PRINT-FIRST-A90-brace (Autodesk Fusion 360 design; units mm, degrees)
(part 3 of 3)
extrude "Extrude2" cut sketch "E Rear Bearing Cap Bolt seed" profile of C1 along normal blind 3 (= "capThickness")
circular_pattern "C-Pattern1" TotalAngle 360
chamfer "Chamfer1" distance 0.3 (= "bedRelief")
work_plane "WorkPlane1" AlongDistance -29 (= "hubFace - adapterThickness") ExtraOffset 0
sketch "F Adapter Flange sketch" plane through (-20.5061, -20.5061, 0) normal (0.7071, 0.7071, 0) x axis (0, 0, 1)
  circle C1 centre (0, 0) radius 38
  dimension "d967" diameter C1 = 76 (= "mountOD")
extrude "Extrude1" new body sketch "F Adapter Flange sketch" along normal blind 6 (= "adapterThickness")
work_plane "WorkPlane2" AlongDistance -23 (= "hubFace") ExtraOffset 0
sketch "F Centering Pilot sketch" plane through (-16.2635, -16.2635, 0) normal (0.7071, 0.7071, 0) x axis (0, 0, 1)
  circle C1 centre (0, 0) radius 25
  circle C2 centre (0, 0) radius 17
  dimension "d972" diameter C1 = 50 (= "pilotDiameter")
  dimension "d973" diameter C2 = 34 (= "pilotInside")
extrude "Extrude2" add sketch "F Centering Pilot sketch" along normal blind 2 (= "pilotHeight")
work_plane "WorkPlane3" AlongDistance -29 (= "hubFace - adapterThickness") ExtraOffset 0
sketch "F Shaft Clearance sketch" plane through (-20.5061, -20.5061, 0) normal (0.7071, 0.7071, 0) x axis (0, 0, 1)
  circle C1 centre (0, 0) radius 4.25
  dimension "d978" diameter C1 = 8.5 (= "shaftClearance")
extrude "Extrude3" cut sketch "F Shaft Clearance sketch" along normal blind 6 (= "adapterThickness")
work_plane "WorkPlane4" AlongDistance -29 (= "hubFace - adapterThickness") ExtraOffset 0
sketch "F Mount Holes" plane through (-20.5061, -20.5061, 0) normal (0.7071, 0.7071, 0) x axis (0, 0, 1)
  circle C1 centre (22.6274, 22.6274) radius 2.15
  circle C2 centre (-22.6274, 22.6274) radius 2.15
  circle C3 centre (-22.6274, -22.6274) radius 2.15
  circle C4 centre (22.6274, -22.6274) radius 2.15
  point P1 (0, 0)
  point P2 (22.6274, 22.6274)
  point P3 (-22.6274, 22.6274)
  point P4 (-22.6274, -22.6274)
  point P5 (22.6274, -22.6274)
  dimension "d983" distance P1 P2 = 22.6274 (= "abs(mountCircle / ( 2 * sqrt(2) ))")
  dimension "d984" distance P1 P2 = 22.6274 (= "abs(mountCircle / ( 2 * sqrt(2) ))")
  dimension "d985" diameter C1 = 4.3 (= "m4Clearance")
  dimension "d986" distance P1 P3 = 22.6274 (= "abs(-mountCircle / ( 2 * sqrt(2) ))")
  dimension "d987" distance P1 P3 = 22.6274 (= "abs(mountCircle / ( 2 * sqrt(2) ))")
  dimension "d988" diameter C2 = 4.3 (= "m4Clearance")
  dimension "d989" distance P1 P4 = 22.6274 (= "abs(-mountCircle / ( 2 * sqrt(2) ))")
  dimension "d990" distance P1 P4 = 22.6274 (= "abs(-mountCircle / ( 2 * sqrt(2) ))")
  dimension "d991" diameter C3 = 4.3 (= "m4Clearance")
  dimension "d992" distance P1 P5 = 22.6274 (= "abs(mountCircle / ( 2 * sqrt(2) ))")
  dimension "d993" distance P1 P5 = 22.6274 (= "abs(-mountCircle / ( 2 * sqrt(2) ))")
  dimension "d994" diameter C4 = 4.3 (= "m4Clearance")
extrude "Extrude4" cut sketch "F Mount Holes" along normal blind 6 (= "adapterThickness")
sketch "F Compression Sleeve Holes" plane through (-20.5061, -20.5061, 0) normal (0.7071, 0.7071, 0) x axis (0, 0, 1)
  line L1 (11.3137, 0) -> (0, 0)
  line L2 (0, 11.3137) -> (0, 0)
  line L3 (-11.3137, 0) -> (0, 0)
  line L4 (0, -11.3137) -> (0, 0)
  circle C1 centre (11.3137, 0) radius 4.1
  circle C2 centre (0, 11.3137) radius 4.1
  circle C3 centre (-11.3137, 0) radius 4.1
  circle C4 centre (0, -11.3137) radius 4.1
  point P1 (0, 0)
  point P2 (11.3137, 0)
  point P3 (0, 11.3137)
  point P5 (0, -11.3137)
  horizontal L1
  vertical L2
  horizontal L3
  vertical L4
  dimension "d997" distance P1 P2 = 11.3137 (= "abs(hubHoleSpacing / sqrt(2))")
  dimension "d998" diameter C1 = 8.2 (= "sleeveOD + sleeveAllowance")
  dimension "d999" distance P1 P3 = 11.3137 (= "abs(hubHoleSpacing / sqrt(2))")
  dimension "d1000" diameter C2 = 8.2 (= "sleeveOD + sleeveAllowance")
  dimension "d59" = 150 (= "bodyWidth")
  dimension "d1002" diameter C3 = 8.2 (= "sleeveOD + sleeveAllowance")
  dimension "d1003" distance P1 P5 = 11.3137 (= "abs(-hubHoleSpacing / sqrt(2))")
  dimension "d1004" diameter C4 = 8.2 (= "sleeveOD + sleeveAllowance")
  dimension "d1001" distance = 11.3137 (= "abs(-hubHoleSpacing / sqrt(2))")
extrude "Extrude5" cut sketch "F Compression Sleeve Holes" profile of C1 C2 C3 C4 along normal blind 6 (= "adapterThickness")
chamfer "Chamfer1" distance 0.4 (= "entryChamfer")
chamfer "Chamfer2" distance 0.3 (= "bedRelief")
work_plane "WorkPlane1" AlongDistance 0.5 (= "qFront") ExtraOffset 0
sketch "Front 608 sketch" plane through (0.3536, 0.3536, 0) normal (0.7071, 0.7071, 0) x axis (0, 0, 1)
  circle C1 centre (0, 0) radius 11
  circle C2 centre (0, 0) radius 4
  dimension "d1011" diameter C1 = 22 (= "bearingOD")
  dimension "d1012" diameter C2 = 8 (= "bearingID")
extrude "Extrude1" new body sketch "Front 608 sketch" along normal blind 7 (= "bearingWidth")
work_plane "WorkPlane2" AlongDistance 25.6 (= "qRearBearing") ExtraOffset 0
sketch "Rear 608 sketch" plane through (18.1019, 18.1019, 0) normal (0.7071, 0.7071, 0) x axis (0, 0, 1)
  circle C1 centre (0, 0) radius 11
  circle C2 centre (0, 0) radius 4
  dimension "d1017" diameter C1 = 22 (= "bearingOD")
  dimension "d1018" diameter C2 = 8 (= "bearingID")
extrude "Extrude2" new body sketch "Rear 608 sketch" along normal blind 7 (= "bearingWidth")
work_plane "WorkPlane1" AlongDistance -24 ExtraOffset 0
sketch "Metal Shaft sketch" plane through (-16.9706, -16.9706, 0) normal (0.7071, 0.7071, 0) x axis (0, 0, 1)
  circle C1 centre (0, 0) radius 4
  dimension "d1023" diameter C1 = 8
extrude "Extrude1" new body sketch "Metal Shaft sketch" along normal blind 60
work_plane "WorkPlane1" AlongDistance -3.5 (= "qFront - 4 mm") ExtraOffset 0
sketch "Front Inner Ring Spacer sketch" plane through (-2.4749, -2.4749, 0) normal (0.7071, 0.7071, 0) x axis (0, 0, 1)
  circle C1 centre (0, 0) radius 5
  circle C2 centre (0, 0) radius 4
  dimension "d1028" diameter C1 = 10
  dimension "d1029" diameter C2 = 8
extrude "Extrude1" new body sketch "Front Inner Ring Spacer sketch" along normal blind 4
work_plane "WorkPlane2" AlongDistance 7.5 (= "qFront + bearingWidth") ExtraOffset 0
sketch "Rear Inner Ring Spacer sketch" plane through (5.3033, 5.3033, 0) normal (0.7071, 0.7071, 0) x axis (0, 0, 1)
  circle C1 centre (0, 0) radius 5
  circle C2 centre (0, 0) radius 4
  dimension "d1034" diameter C1 = 10
  dimension "d1035" diameter C2 = 8
extrude "Extrude2" new body sketch "Rear Inner Ring Spacer sketch" along normal blind 4
work_plane "WorkPlane1" AlongDistance -12.5 (= "qFront - 13 mm") ExtraOffset 0
sketch "Front Collar Maximum Envelope sketch" plane through (-8.8388, -8.8388, 0) normal (0.7071, 0.7071, 0) x axis (0, 0, 1)
  circle C1 centre (0, 0) radius 11.2
  circle C2 centre (0, 0) radius 4
  dimension "d1040" diameter C1 = 22.4
  dimension "d1041" diameter C2 = 8
extrude "Extrude1" new body sketch "Front Collar Maximum Envelope sketch" along normal blind 9
work_plane "WorkPlane2" AlongDistance 11.5 (= "qFront + bearingWidth + 4 mm") ExtraOffset 0
sketch "Rear Collar Maximum Envelope sketch" plane through (8.1317, 8.1317, 0) normal (0.7071, 0.7071, 0) x axis (0, 0, 1)
  circle C1 centre (0, 0) radius 11.2
  circle C2 centre (0, 0) radius 4
  dimension "d1046" diameter C1 = 22.4
  dimension "d1047" diameter C2 = 8
extrude "Extrude2" new body sketch "Rear Collar Maximum Envelope sketch" along normal blind 9
work_plane "WorkPlane1" AlongDistance 0 ExtraOffset 0
sketch "Spacer Pattern Axis" plane through (0, 0, 0) normal (0.7071, 0.7071, 0) x axis (0, 0, 1)
  circle C1 centre (0, 0) radius 0.5
  dimension "d1052" diameter C1 = 1
work_plane "WorkPlane2" AlongDistance 10.6 (= "qFrontBack") ExtraOffset 0
sketch "Support Spacer OD" plane through (7.4953, 7.4953, 0) normal (0.7071, 0.7071, 0) x axis (0, 0, 1)
  line L1 (17, 0) -> (0, 0)
  circle C1 centre (17, 0) radius 3
  circle C2 centre (17, 0) radius 1.6
  point P1 (0, 0)
  point P2 (17, 0)
  horizontal L1
  dimension "d1055" distance P1 P2 = 17 (= "supportCircle / 2")
  dimension "d1056" diameter C1 = 6 (= "supportSpacerOD")
  dimension "d1057" diameter C2 = 3.2
extrude "Extrude1" new body sketch "Support Spacer OD" profile of C1 C2 along normal blind 12 (= "supportSpacer")
circular_pattern "C-Pattern1" TotalAngle 360
work_plane "WorkPlane1" AlongDistance -29 (= "hubFace - adapterThickness") ExtraOffset 0
sketch "Sleeve 1 Outer" plane through (-20.5061, -20.5061, 0) normal (0.7071, 0.7071, 0) x axis (0, 0, 1)
  line L1 (11.3137, 0) -> (0, 0)
  circle C1 centre (11.3137, 0) radius 4
  circle C2 centre (11.3137, 0) radius 2.15
  point P1 (0, 0)
  point P2 (11.3137, 0)
  horizontal L1
  dimension "d1064" distance P1 P2 = 11.3137 (= "abs(hubHoleSpacing / sqrt(2))")
  dimension "d1065" diameter C1 = 8 (= "sleeveOD")
  dimension "d1066" diameter C2 = 4.3
extrude "Extrude1" new body sketch "Sleeve 1 Outer" profile of C1 C2 along normal blind 6 (= "adapterThickness")
work_plane "WorkPlane2" AlongDistance -29 (= "hubFace - adapterThickness") ExtraOffset 0
sketch "Sleeve 2 Outer" plane through (-20.5061, -20.5061, 0) normal (0.7071, 0.7071, 0) x axis (0, 0, 1)
  line L1 (0, 11.3137) -> (0, 0)
  circle C1 centre (0, 11.3137) radius 4
  circle C2 centre (0, 11.3137) radius 2.15
  point P1 (0, 0)
  point P2 (0, 11.3137)
  vertical L1
  dimension "d1071" distance P1 P2 = 11.3137 (= "abs(hubHoleSpacing / sqrt(2))")
  dimension "d1072" diameter C1 = 8 (= "sleeveOD")
  dimension "d1073" diameter C2 = 4.3
extrude "Extrude2" new body sketch "Sleeve 2 Outer" profile of C1 C2 along normal blind 6 (= "adapterThickness")
work_plane "WorkPlane3" AlongDistance -29 (= "hubFace - adapterThickness") ExtraOffset 0
sketch "Sleeve 3 Outer" plane through (-20.5061, -20.5061, 0) normal (0.7071, 0.7071, 0) x axis (0, 0, 1)
  line L1 (-11.3137, 0) -> (0, 0)
  circle C1 centre (-11.3137, 0) radius 4
  circle C2 centre (-11.3137, 0) radius 2.15
  point P1 (0, 0)
  point P2 (-11.3137, 0)
  horizontal L1
  dimension "d1078" distance P1 P2 = 11.3137 (= "abs(-hubHoleSpacing / sqrt(2))")
  dimension "d1079" diameter C1 = 8 (= "sleeveOD")
  dimension "d1080" diameter C2 = 4.3
extrude "Extrude3" new body sketch "Sleeve 3 Outer" profile of C1 C2 along normal blind 6 (= "adapterThickness")
work_plane "WorkPlane4" AlongDistance -29 (= "hubFace - adapterThickness") ExtraOffset 0
sketch "Sleeve 4 Outer" plane through (-20.5061, -20.5061, 0) normal (0.7071, 0.7071, 0) x axis (0, 0, 1)
  line L1 (0, -11.3137) -> (0, 0)
  circle C1 centre (0, -11.3137) radius 4
  circle C2 centre (0, -11.3137) radius 2.15
  point P1 (0, 0)
  point P2 (0, -11.3137)
  vertical L1
  dimension "d1085" distance P1 P2 = 11.3137 (= "abs(-hubHoleSpacing / sqrt(2))")
  dimension "d1086" diameter C1 = 8 (= "sleeveOD")
  dimension "d1087" diameter C2 = 4.3
extrude "Extrude4" new body sketch "Sleeve 4 Outer" profile of C1 C2 along normal blind 6 (= "adapterThickness")
work_plane "WorkPlane1" AlongDistance -23 (= "hubFace") ExtraOffset 0
sketch "Sonic Hub Body sketch" plane through (-16.2635, -16.2635, 0) normal (0.7071, 0.7071, 0) x axis (0, 0, 1)
  circle C1 centre (0, 0) radius 16
  circle C2 centre (0, 0) radius 4
  dimension "d1092" diameter C1 = 32
  dimension "d1093" diameter C2 = 8
extrude "Extrude1" new body sketch "Sonic Hub Body sketch" along normal blind 8
work_plane "WorkPlane2" AlongDistance -15 (= "hubFace + 8 mm") ExtraOffset 0
sketch "Sonic Hub Pilot sketch" plane through (-10.6066, -10.6066, 0) normal (0.7071, 0.7071, 0) x axis (0, 0, 1)
  circle C1 centre (0, 0) radius 7
  circle C2 centre (0, 0) radius 4
  dimension "d1098" diameter C1 = 14
  dimension "d1099" diameter C2 = 8
extrude "Extrude2" add sketch "Sonic Hub Pilot sketch" along normal blind 2
work_plane "WorkPlane3" AlongDistance -23 (= "hubFace") ExtraOffset 0
sketch "Hub M4 Thread Envelopes" plane through (-16.2635, -16.2635, 0) normal (0.7071, 0.7071, 0) x axis (0, 0, 1)
  line L1 (11.3137, 0) -> (0, 0)
  line L2 (0, 11.3137) -> (0, 0)
  line L3 (-11.3137, 0) -> (0, 0)
  line L4 (0, -11.3137) -> (0, 0)
  circle C1 centre (11.3137, 0) radius 2.15
  circle C2 centre (0, 11.3137) radius 2.15
  circle C3 centre (-11.3137, 0) radius 2.15
  circle C4 centre (0, -11.3137) radius 2.15
  point P1 (0, 0)
  point P2 (11.3137, 0)
  point P3 (0, 11.3137)
  point P5 (0, -11.3137)
  horizontal L1
  vertical L2
  horizontal L3
  vertical L4
  dimension "d1104" distance P1 P2 = 11.3137 (= "abs(hubHoleSpacing / sqrt(2))")
  dimension "d1105" diameter C1 = 4.3
  dimension "d1106" distance P1 P3 = 11.3137 (= "abs(hubHoleSpacing / sqrt(2))")
  dimension "d1107" diameter C2 = 4.3
  dimension "d59" = 150 (= "bodyWidth")
  dimension "d1109" diameter C3 = 4.3
  dimension "d1110" distance P1 P5 = 11.3137 (= "abs(-hubHoleSpacing / sqrt(2))")
  dimension "d1111" diameter C4 = 4.3
  dimension "d1108" distance = 11.3137 (= "abs(-hubHoleSpacing / sqrt(2))")
extrude "Extrude3" cut sketch "Hub M4 Thread Envelopes" profile of C1 C2 C3 C4 along normal blind 8
work_plane "WorkPlane1" AlongDistance -30 (= "hubFace - adapterThickness - 1 mm") ExtraOffset 0
sketch "Hub Screw 1 Profile" plane through (-21.2132, -21.2132, 0) normal (0.7071, 0.7071, 0) x axis (0, 0, 1)
  line L1 (11.3137, 0) -> (0, 0)
  circle C1 centre (11.3137, 0) radius 2
  point P1 (0, 0)
  point P2 (11.3137, 0)
  horizontal L1
  dimension "d1116" distance P1 P2 = 11.3137 (= "abs(hubHoleSpacing / sqrt(2))")
  dimension "d1117" diameter C1 = 4
extrude "Extrude1" new body sketch "Hub Screw 1 Profile" profile of C1 along normal blind 12
work_plane "WorkPlane2" AlongDistance -34 (= "hubFace - adapterThickness - 5 mm") ExtraOffset 0
sketch "Hub Screw Head 1 Profile" plane through (-24.0416, -24.0416, 0) normal (0.7071, 0.7071, 0) x axis (0, 0, 1)
  line L1 (11.3137, 0) -> (0, 0)
  circle C1 centre (11.3137, 0) radius 3.5
  point P1 (0, 0)
  point P2 (11.3137, 0)
  horizontal L1
  dimension "d1122" distance P1 P2 = 11.3137 (= "abs(hubHoleSpacing / sqrt(2))")
  dimension "d1123" diameter C1 = 7
extrude "Extrude2" new body sketch "Hub Screw Head 1 Profile" profile of C1 along normal blind 4
work_plane "WorkPlane3" AlongDistance -30 (= "hubFace - adapterThickness - 1 mm") ExtraOffset 0
sketch "Hub Washer 1 Outer" plane through (-21.2132, -21.2132, 0) normal (0.7071, 0.7071, 0) x axis (0, 0, 1)
  line L1 (11.3137, 0) -> (0, 0)
  circle C1 centre (11.3137, 0) radius 6
  circle C2 centre (11.3137, 0) radius 2.15
  point P1 (0, 0)
  point P2 (11.3137, 0)
  horizontal L1
  dimension "d1128" distance P1 P2 = 11.3137 (= "abs(hubHoleSpacing / sqrt(2))")
  dimension "d1129" diameter C1 = 12
  dimension "d1130" diameter C2 = 4.3
extrude "Extrude3" new body sketch "Hub Washer 1 Outer" profile of C1 C2 along normal blind 1
work_plane "WorkPlane4" AlongDistance -30 (= "hubFace - adapterThickness - 1 mm") ExtraOffset 0
sketch "Hub Screw 2 Profile" plane through (-21.2132, -21.2132, 0) normal (0.7071, 0.7071, 0) x axis (0, 0, 1)
  line L1 (0, 11.3137) -> (0, 0)
  circle C1 centre (0, 11.3137) radius 2
  point P1 (0, 0)
  point P2 (0, 11.3137)
  vertical L1
  dimension "d1135" distance P1 P2 = 11.3137 (= "abs(hubHoleSpacing / sqrt(2))")
  dimension "d1136" diameter C1 = 4
extrude "Extrude4" new body sketch "Hub Screw 2 Profile" profile of C1 along normal blind 12
work_plane "WorkPlane5" AlongDistance -34 (= "hubFace - adapterThickness - 5 mm") ExtraOffset 0
sketch "Hub Screw Head 2 Profile" plane through (-24.0416, -24.0416, 0) normal (0.7071, 0.7071, 0) x axis (0, 0, 1)
  line L1 (0, 11.3137) -> (0, 0)
  circle C1 centre (0, 11.3137) radius 3.5
  point P1 (0, 0)
  point P2 (0, 11.3137)
  vertical L1
  dimension "d1141" distance P1 P2 = 11.3137 (= "abs(hubHoleSpacing / sqrt(2))")
  dimension "d1142" diameter C1 = 7
extrude "Extrude5" new body sketch "Hub Screw Head 2 Profile" profile of C1 along normal blind 4
work_plane "WorkPlane6" AlongDistance -30 (= "hubFace - adapterThickness - 1 mm") ExtraOffset 0
sketch "Hub Washer 2 Outer" plane through (-21.2132, -21.2132, 0) normal (0.7071, 0.7071, 0) x axis (0, 0, 1)
  line L1 (0, 11.3137) -> (0, 0)
  circle C1 centre (0, 11.3137) radius 6
  circle C2 centre (0, 11.3137) radius 2.15
  point P1 (0, 0)
  point P2 (0, 11.3137)
  vertical L1
  dimension "d1147" distance P1 P2 = 11.3137 (= "abs(hubHoleSpacing / sqrt(2))")
  dimension "d1148" diameter C1 = 12
  dimension "d1149" diameter C2 = 4.3
extrude "Extrude6" new body sketch "Hub Washer 2 Outer" profile of C1 C2 along normal blind 1
work_plane "WorkPlane7" AlongDistance -30 (= "hubFace - adapterThickness - 1 mm") ExtraOffset 0
sketch "Hub Screw 3 Profile" plane through (-21.2132, -21.2132, 0) normal (0.7071, 0.7071, 0) x axis (0, 0, 1)
  line L1 (-11.3137, 0) -> (0, 0)
  circle C1 centre (-11.3137, 0) radius 2
  point P1 (0, 0)
  point P2 (-11.3137, 0)
  horizontal L1
  dimension "d1154" distance P1 P2 = 11.3137 (= "abs(-hubHoleSpacing / sqrt(2))")
  dimension "d1155" diameter C1 = 4
extrude "Extrude7" new body sketch "Hub Screw 3 Profile" profile of C1 along normal blind 12
work_plane "WorkPlane8" AlongDistance -34 (= "hubFace - adapterThickness - 5 mm") ExtraOffset 0
sketch "Hub Screw Head 3 Profile" plane through (-24.0416, -24.0416, 0) normal (0.7071, 0.7071, 0) x axis (0, 0, 1)
  line L1 (-11.3137, 0) -> (0, 0)
  circle C1 centre (-11.3137, 0) radius 3.5
  point P1 (0, 0)
  point P2 (-11.3137, 0)
  horizontal L1
  dimension "d1160" distance P1 P2 = 11.3137 (= "abs(-hubHoleSpacing / sqrt(2))")
  dimension "d1161" diameter C1 = 7
extrude "Extrude8" new body sketch "Hub Screw Head 3 Profile" profile of C1 along normal blind 4
work_plane "WorkPlane9" AlongDistance -30 (= "hubFace - adapterThickness - 1 mm") ExtraOffset 0
sketch "Hub Washer 3 Outer" plane through (-21.2132, -21.2132, 0) normal (0.7071, 0.7071, 0) x axis (0, 0, 1)
  line L1 (-11.3137, 0) -> (0, 0)
  circle C1 centre (-11.3137, 0) radius 6
  circle C2 centre (-11.3137, 0) radius 2.15
  point P1 (0, 0)
  point P2 (-11.3137, 0)
  horizontal L1
  dimension "d1166" distance P1 P2 = 11.3137 (= "abs(-hubHoleSpacing / sqrt(2))")
  dimension "d1167" diameter C1 = 12
  dimension "d1168" diameter C2 = 4.3
extrude "Extrude9" new body sketch "Hub Washer 3 Outer" profile of C1 C2 along normal blind 1
work_plane "WorkPlane10" AlongDistance -30 (= "hubFace - adapterThickness - 1 mm") ExtraOffset 0
sketch "Hub Screw 4 Profile" plane through (-21.2132, -21.2132, 0) normal (0.7071, 0.7071, 0) x axis (0, 0, 1)
  line L1 (0, -11.3137) -> (0, 0)
  circle C1 centre (0, -11.3137) radius 2
  point P1 (0, 0)
  point P2 (0, -11.3137)
  vertical L1
  dimension "d1173" distance P1 P2 = 11.3137 (= "abs(-hubHoleSpacing / sqrt(2))")
  dimension "d1174" diameter C1 = 4
extrude "Extrude10" new body sketch "Hub Screw 4 Profile" profile of C1 along normal blind 12
work_plane "WorkPlane11" AlongDistance -34 (= "hubFace - adapterThickness - 5 mm") ExtraOffset 0
sketch "Hub Screw Head 4 Profile" plane through (-24.0416, -24.0416, 0) normal (0.7071, 0.7071, 0) x axis (0, 0, 1)
  line L1 (0, -11.3137) -> (0, 0)
  circle C1 centre (0, -11.3137) radius 3.5
  point P1 (0, 0)
  point P2 (0, -11.3137)
  vertical L1
  dimension "d1179" distance P1 P2 = 11.3137 (= "abs(-hubHoleSpacing / sqrt(2))")
  dimension "d1180" diameter C1 = 7
extrude "Extrude11" new body sketch "Hub Screw Head 4 Profile" profile of C1 along normal blind 4
work_plane "WorkPlane12" AlongDistance -30 (= "hubFace - adapterThickness - 1 mm") ExtraOffset 0
sketch "Hub Washer 4 Outer" plane through (-21.2132, -21.2132, 0) normal (0.7071, 0.7071, 0) x axis (0, 0, 1)
  line L1 (0, -11.3137) -> (0, 0)
  circle C1 centre (0, -11.3137) radius 6
  circle C2 centre (0, -11.3137) radius 2.15
  point P1 (0, 0)
  point P2 (0, -11.3137)
  vertical L1
  dimension "d1185" distance P1 P2 = 11.3137 (= "abs(-hubHoleSpacing / sqrt(2))")
  dimension "d1186" diameter C1 = 12
  dimension "d1187" diameter C2 = 4.3
extrude "Extrude12" new body sketch "Hub Washer 4 Outer" profile of C1 C2 along normal blind 1
work_plane "WorkPlane1" AlongDistance -30 (= "hubFace - adapterThickness - 1 mm") ExtraOffset 0
sketch "Adapter Screw 1 Profile" plane through (-21.2132, -21.2132, 0) normal (0.7071, 0.7071, 0) x axis (0, 0, 1)
  circle C1 centre (22.6274, 22.6274) radius 2
  point P1 (0, 0)
  point P2 (22.6274, 22.6274)
  dimension "d1192" distance P1 P2 = 22.6274 (= "abs(mountCircle / ( 2 * sqrt(2) ))")
  dimension "d1193" distance P1 P2 = 22.6274 (= "abs(mountCircle / ( 2 * sqrt(2) ))")
  dimension "d1194" diameter C1 = 4
extrude "Extrude1" new body sketch "Adapter Screw 1 Profile" along normal blind 30
work_plane "WorkPlane2" AlongDistance -34 (= "hubFace - adapterThickness - 5 mm") ExtraOffset 0
sketch "Adapter Screw Head 1 Profile" plane through (-24.0416, -24.0416, 0) normal (0.7071, 0.7071, 0) x axis (0, 0, 1)
  circle C1 centre (22.6274, 22.6274) radius 3.5
  point P1 (0, 0)
  point P2 (22.6274, 22.6274)
  dimension "d1199" distance P1 P2 = 22.6274 (= "abs(mountCircle / ( 2 * sqrt(2) ))")
  dimension "d1200" distance P1 P2 = 22.6274 (= "abs(mountCircle / ( 2 * sqrt(2) ))")
  dimension "d1201" diameter C1 = 7
extrude "Extrude2" new body sketch "Adapter Screw Head 1 Profile" along normal blind 4
work_plane "WorkPlane3" AlongDistance -30 (= "hubFace - adapterThickness - 1 mm") ExtraOffset 0
sketch "Adapter Washer 1 Outer" plane through (-21.2132, -21.2132, 0) normal (0.7071, 0.7071, 0) x axis (0, 0, 1)
  circle C1 centre (22.6274, 22.6274) radius 4.5
  circle C2 centre (22.6274, 22.6274) radius 2.15
  point P1 (0, 0)
  point P2 (22.6274, 22.6274)
  dimension "d1206" distance P1 P2 = 22.6274 (= "abs(mountCircle / ( 2 * sqrt(2) ))")
  dimension "d1207" distance P1 P2 = 22.6274 (= "abs(mountCircle / ( 2 * sqrt(2) ))")
  dimension "d1208" diameter C1 = 9
  dimension "d1209" diameter C2 = 4.3
extrude "Extrude3" new body sketch "Adapter Washer 1 Outer" along normal blind 1
work_plane "WorkPlane4" ExtraOffset 0
sketch "Adapter Nut Hex 1" plane through (-3.182, -3.182, 0) normal (0.7071, 0.7071, 0) x axis (0, 0, 1)
  line L1 (24.6481, 26.1274) -> (26.6689, 22.6274)
  line L2 (20.6067, 26.1274) -> (24.6481, 26.1274)
  line L3 (18.586, 22.6274) -> (20.6067, 26.1274)
  line L4 (20.6067, 19.1274) -> (18.586, 22.6274)
  line L5 (24.6481, 19.1274) -> (20.6067, 19.1274)
  line L6 (26.6689, 22.6274) -> (24.6481, 19.1274)
  circle C1 centre (22.6274, 22.6274) radius 4.0415
  point P3 (26.6689, 22.6274)
  point P4 (24.6481, 26.1274)
  point P5 (20.6067, 26.1274)
  point P6 (18.586, 22.6274)
  point P7 (20.6067, 19.1274)
  point P8 (24.6481, 19.1274)
  point P1 (0, 0)
  point P2 (22.6274, 22.6274)
  coincident C1 P3
  coincident C1 P4
  coincident C1 P5
  coincident C1 P6
  coincident C1 P7
  coincident C1 P8
  equal L1 L2
  equal L1 L3
  equal L1 L4
  equal L1 L5
  equal L1 L6
  horizontal L2
  dimension "d1214" distance P1 P2 = 22.6274 (= "abs(mountCircle / ( 2 * sqrt(2) ))")
  dimension "d1215" distance P1 P2 = 22.6274 (= "abs(mountCircle / ( 2 * sqrt(2) ))")
  dimension "d1216" diameter C1 = 8.0829 (= "2 * ( 7 mm ) / sqrt(3)")
extrude "Extrude4" new body sketch "Adapter Nut Hex 1" profile of L1 L2 L3 L4 L5 L6 along normal blind 3.2
sketch "Nut Thread Clearance 1" plane through (-3.182, -3.182, 0) normal (0.7071, 0.7071, 0) x axis (0, 0, 1)
  circle C1 centre (22.6274, 22.6274) radius 2.15
  point P1 (0, 0)
  point P2 (22.6274, 22.6274)
  dimension "d1219" distance P1 P2 = 22.6274 (= "abs(mountCircle / ( 2 * sqrt(2) ))")
  dimension "d1220" distance P1 P2 = 22.6274 (= "abs(mountCircle / ( 2 * sqrt(2) ))")
  dimension "d1221" diameter C1 = 4.3
extrude "Extrude5" cut sketch "Nut Thread Clearance 1" along normal blind 3.2
work_plane "WorkPlane5" AlongDistance -30 (= "hubFace - adapterThickness - 1 mm") ExtraOffset 0
sketch "Adapter Screw 2 Profile" plane through (-21.2132, -21.2132, 0) normal (0.7071, 0.7071, 0) x axis (0, 0, 1)
  circle C1 centre (-22.6274, 22.6274) radius 2
  point P1 (0, 0)
  point P2 (-22.6274, 22.6274)
  dimension "d1226" distance P1 P2 = 22.6274 (= "abs(-mountCircle / ( 2 * sqrt(2) ))")
  dimension "d1227" distance P1 P2 = 22.6274 (= "abs(mountCircle / ( 2 * sqrt(2) ))")
  dimension "d1228" diameter C1 = 4
extrude "Extrude6" new body sketch "Adapter Screw 2 Profile" along normal blind 30
work_plane "WorkPlane6" AlongDistance -34 (= "hubFace - adapterThickness - 5 mm") ExtraOffset 0
sketch "Adapter Screw Head 2 Profile" plane through (-24.0416, -24.0416, 0) normal (0.7071, 0.7071, 0) x axis (0, 0, 1)
  circle C1 centre (-22.6274, 22.6274) radius 3.5
  point P1 (0, 0)
  point P2 (-22.6274, 22.6274)
  dimension "d1233" distance P1 P2 = 22.6274 (= "abs(-mountCircle / ( 2 * sqrt(2) ))")
  dimension "d1234" distance P1 P2 = 22.6274 (= "abs(mountCircle / ( 2 * sqrt(2) ))")
  dimension "d1235" diameter C1 = 7
extrude "Extrude7" new body sketch "Adapter Screw Head 2 Profile" along normal blind 4
work_plane "WorkPlane7" AlongDistance -30 (= "hubFace - adapterThickness - 1 mm") ExtraOffset 0
sketch "Adapter Washer 2 Outer" plane through (-21.2132, -21.2132, 0) normal (0.7071, 0.7071, 0) x axis (0, 0, 1)
  circle C1 centre (-22.6274, 22.6274) radius 4.5
  circle C2 centre (-22.6274, 22.6274) radius 2.15
  point P1 (0, 0)
  point P2 (-22.6274, 22.6274)
  dimension "d1240" distance P1 P2 = 22.6274 (= "abs(-mountCircle / ( 2 * sqrt(2) ))")
  dimension "d1241" distance P1 P2 = 22.6274 (= "abs(mountCircle / ( 2 * sqrt(2) ))")
  dimension "d1242" diameter C1 = 9
  dimension "d1243" diameter C2 = 4.3
extrude "Extrude8" new body sketch "Adapter Washer 2 Outer" along normal blind 1
work_plane "WorkPlane8" ExtraOffset 0
sketch "Adapter Nut Hex 2" plane through (-3.182, -3.182, 0) normal (0.7071, 0.7071, 0) x axis (0, 0, 1)
  line L1 (-20.6067, 26.1274) -> (-18.586, 22.6274)
  line L2 (-24.6481, 26.1274) -> (-20.6067, 26.1274)
  line L3 (-26.6689, 22.6274) -> (-24.6481, 26.1274)
  line L4 (-24.6481, 19.1274) -> (-26.6689, 22.6274)
  line L5 (-20.6067, 19.1274) -> (-24.6481, 19.1274)
  line L6 (-18.586, 22.6274) -> (-20.6067, 19.1274)
  circle C1 centre (-22.6274, 22.6274) radius 4.0415
  point P3 (-18.586, 22.6274)
  point P4 (-20.6067, 26.1274)
  point P5 (-24.6481, 26.1274)
  point P6 (-26.6689, 22.6274)
  point P7 (-24.6481, 19.1274)
  point P8 (-20.6067, 19.1274)
  point P1 (0, 0)
  point P2 (-22.6274, 22.6274)
  coincident C1 P3
  coincident C1 P4
  coincident C1 P5
  coincident C1 P6
  coincident C1 P7
  coincident C1 P8
  equal L1 L2
  equal L1 L3
  equal L1 L4
  equal L1 L5
  equal L1 L6
  horizontal L2
  dimension "d1248" distance P1 P2 = 22.6274 (= "abs(-mountCircle / ( 2 * sqrt(2) ))")
  dimension "d1249" distance P1 P2 = 22.6274 (= "abs(mountCircle / ( 2 * sqrt(2) ))")
  dimension "d1250" diameter C1 = 8.0829 (= "2 * ( 7 mm ) / sqrt(3)")
extrude "Extrude9" new body sketch "Adapter Nut Hex 2" profile of L1 L2 L3 L4 L5 L6 along normal blind 3.2
sketch "Nut Thread Clearance 2" plane through (-3.182, -3.182, 0) normal (0.7071, 0.7071, 0) x axis (0, 0, 1)
  circle C1 centre (-22.6274, 22.6274) radius 2.15
  point P1 (0, 0)
  point P2 (-22.6274, 22.6274)
  dimension "d1253" distance P1 P2 = 22.6274 (= "abs(-mountCircle / ( 2 * sqrt(2) ))")
  dimension "d1254" distance P1 P2 = 22.6274 (= "abs(mountCircle / ( 2 * sqrt(2) ))")
  dimension "d1255" diameter C1 = 4.3
extrude "Extrude10" cut sketch "Nut Thread Clearance 2" along normal blind 3.2
work_plane "WorkPlane9" AlongDistance -30 (= "hubFace - adapterThickness - 1 mm") ExtraOffset 0
sketch "Adapter Screw 3 Profile" plane through (-21.2132, -21.2132, 0) normal (0.7071, 0.7071, 0) x axis (0, 0, 1)
  circle C1 centre (-22.6274, -22.6274) radius 2
  point P1 (0, 0)
  point P2 (-22.6274, -22.6274)
  dimension "d1260" distance P1 P2 = 22.6274 (= "abs(-mountCircle / ( 2 * sqrt(2) ))")
  dimension "d1261" distance P1 P2 = 22.6274 (= "abs(-mountCircle / ( 2 * sqrt(2) ))")
  dimension "d1262" diameter C1 = 4
extrude "Extrude11" new body sketch "Adapter Screw 3 Profile" along normal blind 30
work_plane "WorkPlane10" AlongDistance -34 (= "hubFace - adapterThickness - 5 mm") ExtraOffset 0
sketch "Adapter Screw Head 3 Profile" plane through (-24.0416, -24.0416, 0) normal (0.7071, 0.7071, 0) x axis (0, 0, 1)
  circle C1 centre (-22.6274, -22.6274) radius 3.5
  point P1 (0, 0)
  point P2 (-22.6274, -22.6274)
  dimension "d1267" distance P1 P2 = 22.6274 (= "abs(-mountCircle / ( 2 * sqrt(2) ))")
  dimension "d1268" distance P1 P2 = 22.6274 (= "abs(-mountCircle / ( 2 * sqrt(2) ))")
  dimension "d1269" diameter C1 = 7
extrude "Extrude12" new body sketch "Adapter Screw Head 3 Profile" along normal blind 4
work_plane "WorkPlane11" AlongDistance -30 (= "hubFace - adapterThickness - 1 mm") ExtraOffset 0
sketch "Adapter Washer 3 Outer" plane through (-21.2132, -21.2132, 0) normal (0.7071, 0.7071, 0) x axis (0, 0, 1)
  circle C1 centre (-22.6274, -22.6274) radius 4.5
  circle C2 centre (-22.6274, -22.6274) radius 2.15
  point P1 (0, 0)
  point P2 (-22.6274, -22.6274)
  dimension "d1274" distance P1 P2 = 22.6274 (= "abs(-mountCircle / ( 2 * sqrt(2) ))")
  dimension "d1275" distance P1 P2 = 22.6274 (= "abs(-mountCircle / ( 2 * sqrt(2) ))")
  dimension "d1276" diameter C1 = 9
  dimension "d1277" diameter C2 = 4.3
extrude "Extrude13" new body sketch "Adapter Washer 3 Outer" along normal blind 1
work_plane "WorkPlane12" ExtraOffset 0
sketch "Adapter Nut Hex 3" plane through (-3.182, -3.182, 0) normal (0.7071, 0.7071, 0) x axis (0, 0, 1)
  line L1 (-20.6067, -19.1274) -> (-18.586, -22.6274)
  line L2 (-24.6481, -19.1274) -> (-20.6067, -19.1274)
  line L3 (-26.6689, -22.6274) -> (-24.6481, -19.1274)
  line L4 (-24.6481, -26.1274) -> (-26.6689, -22.6274)
  line L5 (-20.6067, -26.1274) -> (-24.6481, -26.1274)
  line L6 (-18.586, -22.6274) -> (-20.6067, -26.1274)
  circle C1 centre (-22.6274, -22.6274) radius 4.0415
  point P3 (-18.586, -22.6274)
  point P4 (-20.6067, -19.1274)
  point P5 (-24.6481, -19.1274)
  point P6 (-26.6689, -22.6274)
  point P7 (-24.6481, -26.1274)
  point P8 (-20.6067, -26.1274)
  point P1 (0, 0)
  point P2 (-22.6274, -22.6274)
  coincident C1 P3
  coincident C1 P4
  coincident C1 P5
  coincident C1 P6
  coincident C1 P7
  coincident C1 P8
  equal L1 L2
  equal L1 L3
  equal L1 L4
  equal L1 L5
  equal L1 L6
  horizontal L2
  dimension "d1282" distance P1 P2 = 22.6274 (= "abs(-mountCircle / ( 2 * sqrt(2) ))")
  dimension "d1283" distance P1 P2 = 22.6274 (= "abs(-mountCircle / ( 2 * sqrt(2) ))")
  dimension "d1284" diameter C1 = 8.0829 (= "2 * ( 7 mm ) / sqrt(3)")
extrude "Extrude14" new body sketch "Adapter Nut Hex 3" profile of L1 L2 L3 L4 L5 L6 along normal blind 3.2
sketch "Nut Thread Clearance 3" plane through (-3.182, -3.182, 0) normal (0.7071, 0.7071, 0) x axis (0, 0, 1)
  circle C1 centre (-22.6274, -22.6274) radius 2.15
  point P1 (0, 0)
  point P2 (-22.6274, -22.6274)
  dimension "d1287" distance P1 P2 = 22.6274 (= "abs(-mountCircle / ( 2 * sqrt(2) ))")
  dimension "d1288" distance P1 P2 = 22.6274 (= "abs(-mountCircle / ( 2 * sqrt(2) ))")
  dimension "d1289" diameter C1 = 4.3
extrude "Extrude15" cut sketch "Nut Thread Clearance 3" along normal blind 3.2
work_plane "WorkPlane13" AlongDistance -30 (= "hubFace - adapterThickness - 1 mm") ExtraOffset 0
sketch "Adapter Screw 4 Profile" plane through (-21.2132, -21.2132, 0) normal (0.7071, 0.7071, 0) x axis (0, 0, 1)
  circle C1 centre (22.6274, -22.6274) radius 2
  point P1 (0, 0)
  point P2 (22.6274, -22.6274)
  dimension "d1294" distance P1 P2 = 22.6274 (= "abs(mountCircle / ( 2 * sqrt(2) ))")
  dimension "d1295" distance P1 P2 = 22.6274 (= "abs(-mountCircle / ( 2 * sqrt(2) ))")
  dimension "d1296" diameter C1 = 4
extrude "Extrude16" new body sketch "Adapter Screw 4 Profile" along normal blind 30
work_plane "WorkPlane14" AlongDistance -34 (= "hubFace - adapterThickness - 5 mm") ExtraOffset 0
sketch "Adapter Screw Head 4 Profile" plane through (-24.0416, -24.0416, 0) normal (0.7071, 0.7071, 0) x axis (0, 0, 1)
  circle C1 centre (22.6274, -22.6274) radius 3.5
  point P1 (0, 0)
  point P2 (22.6274, -22.6274)
  dimension "d1301" distance P1 P2 = 22.6274 (= "abs(mountCircle / ( 2 * sqrt(2) ))")
  dimension "d1302" distance P1 P2 = 22.6274 (= "abs(-mountCircle / ( 2 * sqrt(2) ))")
  dimension "d1303" diameter C1 = 7
extrude "Extrude17" new body sketch "Adapter Screw Head 4 Profile" along normal blind 4
work_plane "WorkPlane15" AlongDistance -30 (= "hubFace - adapterThickness - 1 mm") ExtraOffset 0
sketch "Adapter Washer 4 Outer" plane through (-21.2132, -21.2132, 0) normal (0.7071, 0.7071, 0) x axis (0, 0, 1)
  circle C1 centre (22.6274, -22.6274) radius 4.5
  circle C2 centre (22.6274, -22.6274) radius 2.15
  point P1 (0, 0)
  point P2 (22.6274, -22.6274)
  dimension "d1308" distance P1 P2 = 22.6274 (= "abs(mountCircle / ( 2 * sqrt(2) ))")
  dimension "d1309" distance P1 P2 = 22.6274 (= "abs(-mountCircle / ( 2 * sqrt(2) ))")
  dimension "d1310" diameter C1 = 9
  dimension "d1311" diameter C2 = 4.3
extrude "Extrude18" new body sketch "Adapter Washer 4 Outer" along normal blind 1
work_plane "WorkPlane16" ExtraOffset 0
sketch "Adapter Nut Hex 4" plane through (-3.182, -3.182, 0) normal (0.7071, 0.7071, 0) x axis (0, 0, 1)
  line L1 (24.6481, -19.1274) -> (26.6689, -22.6274)
  line L2 (20.6067, -19.1274) -> (24.6481, -19.1274)
  line L3 (18.586, -22.6274) -> (20.6067, -19.1274)
  line L4 (20.6067, -26.1274) -> (18.586, -22.6274)
  line L5 (24.6481, -26.1274) -> (20.6067, -26.1274)
  line L6 (26.6689, -22.6274) -> (24.6481, -26.1274)
  circle C1 centre (22.6274, -22.6274) radius 4.0415
  point P3 (26.6689, -22.6274)
  point P4 (24.6481, -19.1274)
  point P5 (20.6067, -19.1274)
  point P6 (18.586, -22.6274)
  point P7 (20.6067, -26.1274)
  point P8 (24.6481, -26.1274)
  point P1 (0, 0)
  point P2 (22.6274, -22.6274)
  coincident C1 P3
  coincident C1 P4
  coincident C1 P5
  coincident C1 P6
  coincident C1 P7
  coincident C1 P8
  equal L1 L2
  equal L1 L3
  equal L1 L4
  equal L1 L5
  equal L1 L6
  horizontal L2
  dimension "d1316" distance P1 P2 = 22.6274 (= "abs(mountCircle / ( 2 * sqrt(2) ))")
  dimension "d1317" distance P1 P2 = 22.6274 (= "abs(-mountCircle / ( 2 * sqrt(2) ))")
  dimension "d1318" diameter C1 = 8.0829 (= "2 * ( 7 mm ) / sqrt(3)")
extrude "Extrude19" new body sketch "Adapter Nut Hex 4" profile of L1 L2 L3 L4 L5 L6 along normal blind 3.2
sketch "Nut Thread Clearance 4" plane through (-3.182, -3.182, 0) normal (0.7071, 0.7071, 0) x axis (0, 0, 1)
  circle C1 centre (22.6274, -22.6274) radius 2.15
  point P1 (0, 0)
  point P2 (22.6274, -22.6274)
  dimension "d1321" distance P1 P2 = 22.6274 (= "abs(mountCircle / ( 2 * sqrt(2) ))")
  dimension "d1322" distance P1 P2 = 22.6274 (= "abs(-mountCircle / ( 2 * sqrt(2) ))")
  dimension "d1323" diameter C1 = 4.3
extrude "Extrude20" cut sketch "Nut Thread Clearance 4" along normal blind 3.2
work_plane "WorkPlane1" AlongDistance 0 ExtraOffset 0
sketch "M3 Pattern Axis" plane through (0, 0, 0) normal (0.7071, 0.7071, 0) x axis (0, 0, 1)
  circle C1 centre (0, 0) radius 0.5
  dimension "d1328" diameter C1 = 1
work_plane "WorkPlane2" AlongDistance -8.7 (= "qRearEnd + capThickness + 0.5 mm - 45 mm") ExtraOffset 0
sketch "M3 Shank Profile" plane through (-6.1518, -6.1518, 0) normal (0.7071, 0.7071, 0) x axis (0, 0, 1)
  line L1 (17, 0) -> (0, 0)
  circle C1 centre (17, 0) radius 1.5
  point P1 (0, 0)
  point P2 (17, 0)
  horizontal L1
  dimension "d1331" distance P1 P2 = 17 (= "supportCircle / 2")
  dimension "d1332" diameter C1 = 3
extrude "Extrude1" new body sketch "M3 Shank Profile" profile of C1 along normal blind 45
work_plane "WorkPlane3" AlongDistance 36.3 (= "qRearEnd + capThickness + 0.5 mm") ExtraOffset 0
sketch "M3 Head Profile" plane through (25.668, 25.668, 0) normal (0.7071, 0.7071, 0) x axis (0, 0, 1)
  line L1 (17, 0) -> (0, 0)
  circle C1 centre (17, 0) radius 2.75
  point P1 (0, 0)
  point P2 (17, 0)
  horizontal L1
  dimension "d1337" distance P1 P2 = 17 (= "supportCircle / 2")
  dimension "d1338" diameter C1 = 5.5
extrude "Extrude2" new body sketch "M3 Head Profile" profile of C1 along normal blind 3
work_plane "WorkPlane4" AlongDistance 35.8 (= "qRearEnd + capThickness") ExtraOffset 0
sketch "Rear M3 Washer Profile" plane through (25.3144, 25.3144, 0) normal (0.7071, 0.7071, 0) x axis (0, 0, 1)
  line L1 (17, 0) -> (0, 0)
  circle C1 centre (17, 0) radius 3.5
  circle C2 centre (17, 0) radius 1.65
  point P1 (0, 0)
  point P2 (17, 0)
  horizontal L1
  dimension "d1343" distance P1 P2 = 17 (= "supportCircle / 2")
  dimension "d1344" diameter C1 = 7
  dimension "d1345" diameter C2 = 3.3
extrude "Extrude3" new body sketch "Rear M3 Washer Profile" profile of C1 C2 along normal blind 0.5
work_plane "WorkPlane5" AlongDistance -3 (= "qFront - capThickness - 0.5 mm") ExtraOffset 0
sketch "Front M3 Washer Profile" plane through (-2.1213, -2.1213, 0) normal (0.7071, 0.7071, 0) x axis (0, 0, 1)
  line L1 (17, 0) -> (0, 0)
  circle C1 centre (17, 0) radius 3.5
  circle C2 centre (17, 0) radius 1.65
  point P1 (0, 0)
  point P2 (17, 0)
  horizontal L1
  dimension "d1350" distance P1 P2 = 17 (= "supportCircle / 2")
  dimension "d1351" diameter C1 = 7
  dimension "d1352" diameter C2 = 3.3
extrude "Extrude4" new body sketch "Front M3 Washer Profile" profile of C1 C2 along normal blind 0.5
work_plane "WorkPlane6" AlongDistance -7 (= "qFront - capThickness - 4.5 mm") ExtraOffset 0
sketch "Front M3 Nyloc Envelope Profile" plane through (-4.9497, -4.9497, 0) normal (0.7071, 0.7071, 0) x axis (0, 0, 1)
  line L1 (17, 0) -> (0, 0)
  circle C1 centre (17, 0) radius 3.18
  circle C2 centre (17, 0) radius 1.65
  point P1 (0, 0)
  point P2 (17, 0)
  horizontal L1
  dimension "d1357" distance P1 P2 = 17 (= "supportCircle / 2")
  dimension "d1358" diameter C1 = 6.36
  dimension "d1359" diameter C2 = 3.3
extrude "Extrude5" new body sketch "Front M3 Nyloc Envelope Profile" profile of C1 C2 along normal blind 4
circular_pattern "C-Pattern1" TotalAngle 360
work_plane "WorkPlane25" RotateAngle 90 ExtraOffset 0
work_plane "WorkPlane26" AlongDistance 75 (= "bodyWidth / 2") ExtraOffset 0
sketch "B Driver Pad 1 Slot" plane through (0, -75, 0) normal (0, -1, 0) x axis (-1, 0, 0)
  line L1 (49.5, 16.6274) -> (43, 16.6274)
  line L2 (43, 28.6274) -> (49.5, 28.6274)
  line L3 (49.5, 22.6274) -> (43, 22.6274)
  arc A1 centre (49.5, 22.6274) radius 6 clockwise from (49.5, 28.6274) to (49.5, 16.6274)
  arc A2 centre (43, 22.6274) radius 6 clockwise from (43, 16.6274) to (43, 28.6274)
  point P2 (43, 22.6274)
  point P7 (43, 22.6274)
  point P1 (0, 0)
  point P8 (49.5, 22.6274)
  coincident P2 P7
  tangent L1 A1
  tangent A1 L2
  tangent L2 A2
  tangent L1 A2
  parallel L1 L2
  horizontal L3
  dimension "d1371" distance P1 P2 = 43 (= "Linear Dimension-2")
  dimension "d1372" distance P1 P2 = 22.6274 (= "Linear Dimension-3")
  dimension "d1373" diameter A1 = 12
  dimension "d1374" distance P7 P8 = 6.5
extrude "Extrude44" add sketch "B Driver Pad 1 Slot" profile of L1 A1 L2 A2 no distance stored
sketch "B Driver Pad 2 Slot" plane through (0, -75, 0) normal (0, -1, 0) x axis (-1, 0, 0)
  line L1 (49.5, -28.6274) -> (43, -28.6274)
  line L2 (43, -16.6274) -> (49.5, -16.6274)
  line L3 (49.5, -22.6274) -> (43, -22.6274)
  arc A1 centre (49.5, -22.6274) radius 6 clockwise from (49.5, -16.6274) to (49.5, -28.6274)
  arc A2 centre (43, -22.6274) radius 6 clockwise from (43, -28.6274) to (43, -16.6274)
  point P2 (43, -22.6274)
  point P7 (43, -22.6274)
  point P1 (0, 0)
  point P8 (49.5, -22.6274)
  coincident P2 P7
  tangent L1 A1
  tangent A1 L2
  tangent L2 A2
  tangent L1 A2
  parallel L1 L2
  horizontal L3
  dimension "d1377" distance P1 P2 = 43 (= "Linear Dimension-2")
  dimension "d1378" distance P1 P2 = 22.6274 (= "Linear Dimension-3")
  dimension "d1379" diameter A1 = 12
  dimension "d1380" distance P7 P8 = 6.5
extrude "Extrude45" add sketch "B Driver Pad 2 Slot" profile of L1 A1 L2 A2 no distance stored
sketch "B Driver Pad 3 Slot" plane through (0, -75, 0) normal (0, -1, 0) x axis (-1, 0, 0)
  line L1 (113.5, -28.6274) -> (107, -28.6274)
  line L2 (107, -16.6274) -> (113.5, -16.6274)
  line L3 (113.5, -22.6274) -> (107, -22.6274)
  arc A1 centre (113.5, -22.6274) radius 6 clockwise from (113.5, -16.6274) to (113.5, -28.6274)
  arc A2 centre (107, -22.6274) radius 6 clockwise from (107, -28.6274) to (107, -16.6274)
  point P2 (107, -22.6274)
  point P7 (107, -22.6274)
  point P1 (0, 0)
  point P8 (113.5, -22.6274)
  coincident P2 P7
  tangent L1 A1
  tangent A1 L2
  tangent L2 A2
  tangent L1 A2
  parallel L1 L2
  horizontal L3
  dimension "d1383" distance P1 P2 = 107 (= "Linear Dimension-2")
  dimension "d1384" distance P1 P2 = 22.6274 (= "Linear Dimension-3")
  dimension "d1385" diameter A1 = 12
  dimension "d1386" distance P7 P8 = 6.5
extrude "Extrude46" add sketch "B Driver Pad 3 Slot" profile of L1 A1 L2 A2 no distance stored
sketch "B Driver Pad 4 Slot" plane through (0, -75, 0) normal (0, -1, 0) x axis (-1, 0, 0)
  line L1 (113.5, 16.6274) -> (107, 16.6274)
  line L2 (107, 28.6274) -> (113.5, 28.6274)
  line L3 (113.5, 22.6274) -> (107, 22.6274)
  arc A1 centre (113.5, 22.6274) radius 6 clockwise from (113.5, 28.6274) to (113.5, 16.6274)
  arc A2 centre (107, 22.6274) radius 6 clockwise from (107, 16.6274) to (107, 28.6274)
  point P2 (107, 22.6274)
  point P7 (107, 22.6274)
  point P1 (0, 0)
  point P8 (113.5, 22.6274)
  coincident P2 P7
  tangent L1 A1
  tangent A1 L2
  tangent L2 A2
  tangent L1 A2
  parallel L1 L2
  horizontal L3
  dimension "d1389" distance P1 P2 = 107 (= "Linear Dimension-2")
  dimension "d1390" distance P1 P2 = 22.6274 (= "Linear Dimension-3")
  dimension "d1391" diameter A1 = 12
  dimension "d1392" distance P7 P8 = 6.5
extrude "Extrude47" add sketch "B Driver Pad 4 Slot" profile of L1 A1 L2 A2 no distance stored
work_plane "WorkPlane27" AlongDistance -35 ExtraOffset 0
sketch "B Mount Driver Axes" plane through (-24.7487, -24.7487, 0) normal (0.7071, 0.7071, 0) x axis (0, 0, 1)
  circle C1 centre (22.6274, 22.6274) radius 2.5
  circle C2 centre (-22.6274, 22.6274) radius 2.5
  circle C3 centre (-22.6274, -22.6274) radius 2.5
  circle C4 centre (22.6274, -22.6274) radius 2.5
  point P1 (0, 0)
  point P2 (22.6274, 22.6274)
  point P3 (-22.6274, 22.6274)
  point P4 (-22.6274, -22.6274)
  point P5 (22.6274, -22.6274)
  dimension "d1397" distance P1 P2 = 22.6274 (= "abs(mountCircle / ( 2 * sqrt(2) ))")
  dimension "d1398" distance P1 P2 = 22.6274 (= "abs(mountCircle / ( 2 * sqrt(2) ))")
  dimension "d1399" diameter C1 = 5 (= "driverPort")
  dimension "d1400" distance P1 P3 = 22.6274 (= "abs(-mountCircle / ( 2 * sqrt(2) ))")
  dimension "d1401" distance P1 P3 = 22.6274 (= "abs(mountCircle / ( 2 * sqrt(2) ))")
  dimension "d1402" diameter C2 = 5 (= "driverPort")
  dimension "d1403" distance P1 P4 = 22.6274 (= "abs(-mountCircle / ( 2 * sqrt(2) ))")
  dimension "d1404" distance P1 P4 = 22.6274 (= "abs(-mountCircle / ( 2 * sqrt(2) ))")
  dimension "d1405" diameter C3 = 5 (= "driverPort")
  dimension "d1406" distance P1 P5 = 22.6274 (= "abs(mountCircle / ( 2 * sqrt(2) ))")
  dimension "d1407" distance P1 P5 = 22.6274 (= "abs(-mountCircle / ( 2 * sqrt(2) ))")
  dimension "d1408" diameter C4 = 5 (= "driverPort")
extrude "Extrude48" cut sketch "B Mount Driver Axes" no distance stored
ground "Pin"
as_built_joint "As-built1" RotateMinimum 0 RotateMaximum 180
as_built_joint "As-built2"
as_built_joint "As-built3"
as_built_joint "As-built4"
as_built_joint "As-built5"
as_built_joint "As-built6"
as_built_joint "As-built7"
as_built_joint "As-built8"
as_built_joint "As-built9"
as_built_joint "As-built10"
as_built_joint "As-built11"
as_built_joint "As-built12"
as_built_joint "As-built13"
as_built_joint "As-built14"
as_built_joint "As-built15"
work_plane "WorkPlane33" AlongDistance -35 ExtraOffset 0
sketch "PRINT-FIRST-A0-rim Crop Footprint" plane through (0, 0, -35) normal (0, 0, 1) x axis (1, 0, 0)
  line L1 (130, 66.5) -> (55, 66.5)
  line L2 (130, 75) -> (130, 66.5)
  line L3 (55, 75) -> (130, 75)
  line L4 (55, 66.5) -> (55, 75)
  point P1 (0, 0)
  point P2 (55, 66.5)
  point P3 (130, 66.5)
  point P4 (130, 75)
  point P5 (55, 75)
  dimension "d1451" distance P1 P2 = 55 (= "abs(55 mm)")
  dimension "d1452" distance P1 P2 = 66.5 (= "abs(66.5 mm)")
  dimension "d1453" distance P1 P3 = 130 (= "abs(130 mm)")
  dimension "d1454" distance P1 P3 = 66.5 (= "abs(66.5 mm)")
  dimension "d1455" distance P1 P4 = 130 (= "abs(130 mm)")
  dimension "d1456" distance P1 P4 = 75 (= "abs(75 mm)")
  dimension "d1457" distance P1 P5 = 55 (= "abs(55 mm)")
  dimension "d1458" distance P1 P5 = 75 (= "abs(75 mm)")
extrude "Extrude46" sketch "PRINT-FIRST-A0-rim Crop Footprint" along normal blind 70
work_plane "WorkPlane34" AlongDistance 90.1 ExtraOffset 0
sketch "PRINT-FIRST-A0-rim Level Bed Boundary" plane through (63.7103, 63.7103, 0) normal (0.7071, 0.7071, 0) x axis (0, 0, 1)
  line L1 (200, -200) -> (-200, -200)
  line L2 (200, 200) -> (200, -200)
  line L3 (-200, 200) -> (200, 200)
  line L4 (-200, -200) -> (-200, 200)
  line L5 (200, 200) -> (-200, -200)
  point P1 (0, 0)
  point P2 (-200, -200)
  point P3 (200, -200)
  point P4 (200, 200)
  horizontal L1
  vertical L2
  horizontal L3
  vertical L4
  midpoint P1 L5
  dimension "d1463" distance P2 P3 = 400
  dimension "d1464" distance P3 P4 = 400
extrude "Extrude47" sketch "PRINT-FIRST-A0-rim Level Bed Boundary" profile of L1 L2 L3 L4 along normal blind 300
work_plane "WorkPlane35" AlongDistance 66.5 ExtraOffset 0
sketch "PRINT-FIRST-A90-brace Crop Footprint" plane through (0, 0, 66.5) normal (0, 0, 1) x axis (1, 0, 0)
  line L1 (130, -35) -> (48, -35)
  line L2 (130, 35) -> (130, -35)
  line L3 (48, 35) -> (130, 35)
  line L4 (48, -35) -> (48, 35)
  point P1 (0, 0)
  point P2 (48, -35)
  point P3 (130, -35)
  point P4 (130, 35)
  point P5 (48, 35)
  dimension "d1469" distance P1 P2 = 48 (= "abs(48 mm)")
  dimension "d1470" distance P1 P2 = 35 (= "abs(-35 mm)")
  dimension "d1471" distance P1 P3 = 130 (= "abs(130 mm)")
  dimension "d1472" distance P1 P3 = 35 (= "abs(-35 mm)")
  dimension "d1473" distance P1 P4 = 130 (= "abs(130 mm)")
  dimension "d1474" distance P1 P4 = 35 (= "abs(35 mm)")
  dimension "d1475" distance P1 P5 = 48 (= "abs(48 mm)")
  dimension "d1476" distance P1 P5 = 35 (= "abs(35 mm)")
extrude "Extrude48" sketch "PRINT-FIRST-A90-brace Crop Footprint" along normal blind 8.5 bodies "A Housing print (1)"
work_plane "WorkPlane36" AlongDistance 50.1 ExtraOffset 0
sketch "PRINT-FIRST-A90-brace Level Bed Boundary" plane through (35.426, 35.426, 0) normal (0.7071, 0.7071, 0) x axis (0, 0, 1)
  line L1 (200, -200) -> (-200, -200)
  line L2 (200, 200) -> (200, -200)
  line L3 (-200, 200) -> (200, 200)
  line L4 (-200, -200) -> (-200, 200)
  line L5 (200, 200) -> (-200, -200)
  point P1 (0, 0)
  point P2 (-200, -200)
  point P3 (200, -200)
  point P4 (200, 200)
  horizontal L1
  vertical L2
  horizontal L3
  vertical L4
  midpoint P1 L5
  dimension "d1481" distance P2 P3 = 400
  dimension "d1482" distance P3 P4 = 400
extrude "Extrude49" sketch "PRINT-FIRST-A90-brace Level Bed Boundary" profile of L1 L2 L3 L4 along normal blind 300
remove_body "RemoveBody1"
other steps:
base_feature "Base Feature1" bodies "A Housing print"
base_feature "Base Feature1" bodies "B Moving Body print"
create_component "CreateComponent1"
reparent_decal "ReparentDecal1"
remove_body "RemoveBody1"
create_component "CreateComponent2"
reparent_decal "ReparentDecal2"
remove_body "RemoveBody2"
create_component "CreateComponent3"
create_component "CreateComponent4"
create_component "CreateComponent5"
create_component "CreateComponent6"
create_component "CreateComponent7"
create_component "CreateComponent8"
create_component "CreateComponent9"
create_component "CreateComponent10"
create_component "CreateComponent11"
create_component "CreateComponent12"
create_component "CreateComponent13"
create_component "CreateComponent14"
create_component "CreateComponent15"
create_component "CreateComponent16"
named bodies: "A Housing print", "B Moving Body print", "A Housing print (1)"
